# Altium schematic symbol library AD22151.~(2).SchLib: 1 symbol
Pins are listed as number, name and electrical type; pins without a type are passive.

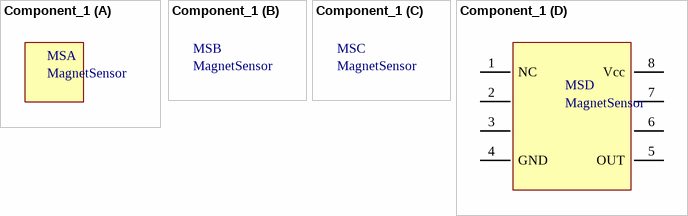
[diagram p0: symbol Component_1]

## Component_1
designator MS, comment MagnetSensor
footprint AD22151 (Magnetic Sensor)
part D pins: 1 NC, 2, 3, 4 GND, 5 OUT, 6, 7, 8 Vcc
